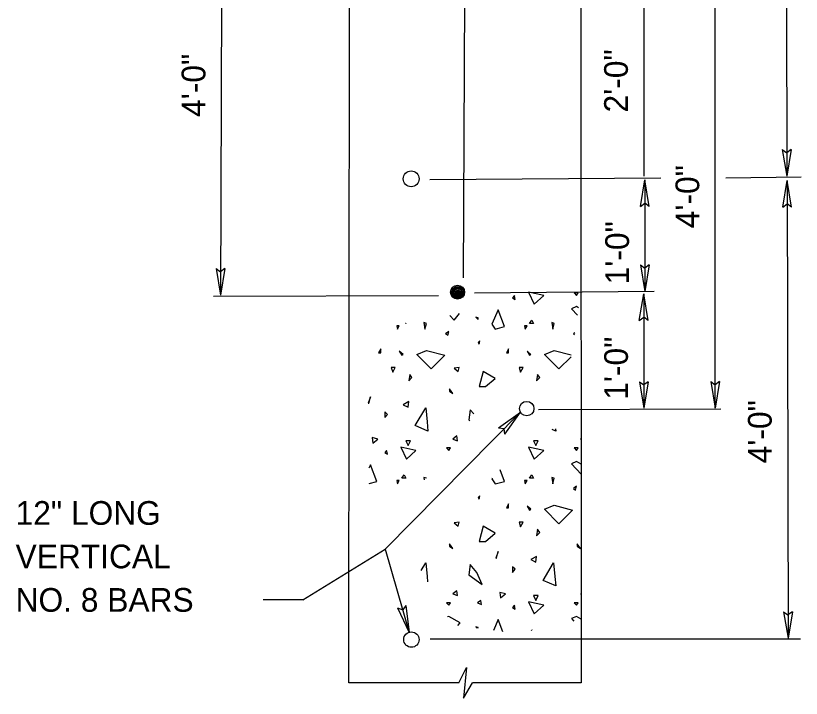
# Model space of a CAD drawing. Extents: x -0.8 to 6.5, y 10.6 to 20.8.
# Drawn here: x 4.207 to 6.193, y 12.966 to 14.693 of the extents above; entities that cross this region are included whole.
import ezdxf

# ---------------------------------------------------------------- set-up
doc = ezdxf.new("R2010")
doc.units = 0
for name, color, linetype in [('DETL-DIMS', 7, 'Continuous'), ('DETL-LINE', 7, 'Continuous'), ('DETL-NOTE', 7, 'Continuous'), ('DETL-PATT', 7, 'Continuous')]:
    doc.layers.add(name, color=color, linetype=linetype)

msp = doc.modelspace()

# ---------------------------------------------------------------- linework, layer by layer
at = {"layer": 'DETL-DIMS'}
for p, q in [((6.1547, 15.4506), (6.1565, 14.2871)), ((4.7284, 15.1604), (4.7241, 13.9861)), ((5.344, 15.1333), (5.338, 14.0301)), ((5.7946, 14.8825), (5.7949, 14.2867)), ((5.9756, 13.7003), (5.9749, 14.883)), ((6.1452, 14.3542), (6.1565, 14.2871)), ((6.1452, 14.3542), (6.1565, 14.3459)), ((6.1677, 14.3542), (6.1565, 14.2871)), ((6.1677, 14.3542), (6.1565, 14.3459)), ((6.002, 14.2831), (6.1932, 14.2851)), ((5.2538, 14.2789), (5.8384, 14.2824)), ((5.7866, 14.2104), (5.7977, 14.2776)), ((5.7977, 14.2776), (5.7972, 13.9956)), ((5.8089, 14.2103), (5.7977, 14.2776)), ((6.1462, 14.2086), (6.1572, 14.2759)), ((6.1572, 14.2759), (6.1597, 13.1183)), ((6.1685, 14.2088), (6.1572, 14.2759)), ((5.7866, 14.2104), (5.7977, 14.2187)), ((5.8089, 14.2103), (5.7977, 14.2187)), ((6.1462, 14.2086), (6.1574, 14.2171)), ((6.1685, 14.2088), (6.1574, 14.2171)), ((4.7131, 14.0534), (4.7241, 13.9861)), ((4.7131, 14.0534), (4.7243, 14.0449)), ((4.7356, 14.0533), (4.7241, 13.9861)), ((4.7356, 14.0533), (4.7243, 14.0449)), ((5.7863, 14.0629), (5.7972, 13.9956)), ((5.7863, 14.0629), (5.7974, 14.0544)), ((5.8086, 14.0628), (5.7972, 13.9956)), ((5.8086, 14.0628), (5.7974, 14.0544)), ((5.3667, 13.9921), (5.8214, 13.9961)), ((5.7836, 13.922), (5.7946, 13.9891)), ((5.7946, 13.9891), (5.7952, 13.7)), ((5.8059, 13.922), (5.7946, 13.9891)), ((4.7064, 13.9838), (5.2758, 13.9855)), ((5.7836, 13.922), (5.7946, 13.9305)), ((5.8059, 13.922), (5.7946, 13.9305)), ((5.7838, 13.7672), (5.7952, 13.7)), ((5.7838, 13.7672), (5.7951, 13.7588)), ((5.8062, 13.7672), (5.7951, 13.7588)), ((5.8062, 13.7672), (5.7952, 13.7)), ((5.9642, 13.7675), (5.9756, 13.7003)), ((5.9642, 13.7675), (5.9756, 13.7592)), ((5.9867, 13.7675), (5.9756, 13.7003)), ((5.9867, 13.7675), (5.9756, 13.7592)), ((5.1409, 13.3439), (5.483, 13.6903)), ((5.4276, 13.6503), (5.483, 13.6903)), ((5.4436, 13.6345), (5.483, 13.6903)), ((5.529, 13.6967), (5.9894, 13.6988)), ((5.4276, 13.6503), (5.4416, 13.6485)), ((5.4436, 13.6345), (5.4416, 13.6485)), ((4.9326, 13.2152), (5.1409, 13.3439)), ((5.1409, 13.3439), (5.2013, 13.1331)), ((4.9326, 13.2152), (4.8326, 13.2152)), ((5.172, 13.1947), (5.2013, 13.1331)), ((5.172, 13.1947), (5.1852, 13.1897)), ((5.1935, 13.2007), (5.1852, 13.1897)), ((5.1935, 13.2007), (5.2013, 13.1331)), ((6.1482, 13.1854), (6.1597, 13.1183)), ((6.1482, 13.1854), (6.1595, 13.1771)), ((6.1707, 13.1854), (6.1595, 13.1771)), ((6.1707, 13.1854), (6.1597, 13.1183)), ((5.2548, 13.1171), (6.1915, 13.1168))]:
    msp.add_line(p, q, dxfattribs=at)
at = {"layer": 'DETL-LINE'}
for p, q in [((5.0487, 13.0051), (5.052, 15.599)), ((5.6349, 15.5982), (5.6368, 13.0051)), ((5.327, 13.0051), (5.3462, 13.0438)), ((5.3462, 13.0438), (5.3392, 12.9663)), ((5.327, 13.0051), (5.0487, 13.0051)), ((5.3392, 12.9663), (5.3615, 13.0051)), ((5.6368, 13.0051), (5.3615, 13.0051))]:
    msp.add_line(p, q, dxfattribs=at)
for centre, radius in [((5.2066, 14.2802), 0.02), ((5.3239, 13.9935), 0.0177), ((5.3244, 13.9925), 0.0155), ((5.3244, 13.9925), 0.0134), ((5.3242, 13.9925), 0.0115), ((5.3248, 13.992), 0.0101), ((5.3253, 13.9908), 0.00797), ((5.3253, 13.9906), 0.0059), ((5.3251, 13.9906), 0.00398), ((5.3255, 13.9906), 0.00188), ((5.4988, 13.6991), 0.0182), ((5.2071, 13.1147), 0.0194)]:
    msp.add_circle(centre, radius, dxfattribs=at)
at = {"layer": 'DETL-PATT'}
for points in [[(5.5035, 13.9935), (5.5178, 13.9631), (5.5418, 13.9853)], [(5.6186, 13.9915), (5.6249, 13.9853), (5.6288, 13.9915)], [(5.4631, 13.979), (5.4693, 13.9751), (5.4675, 13.9853)], [(5.419, 13.9003), (5.443, 13.9065), (5.4266, 13.9488), (5.4108, 13.9128)], [(5.3761, 13.9286), (5.3705, 13.9306), (5.3761, 13.9248)], [(5.1703, 13.9085), (5.1722, 13.9003), (5.1765, 13.9085)], [(5.239, 13.9166), (5.2413, 13.9003), (5.2452, 13.9146)], [(5.4933, 13.9085), (5.4953, 13.9003), (5.4996, 13.9085)], [(5.5116, 13.9228), (5.516, 13.9146), (5.5058, 13.9146)], [(5.562, 13.9166), (5.5645, 13.9003), (5.5683, 13.9146)], [(5.2937, 13.8883), (5.2995, 13.8845), (5.3018, 13.8945)], [(5.3805, 13.8701), (5.3761, 13.8663), (5.3786, 13.862)], [(5.13, 13.85), (5.1242, 13.8398), (5.13, 13.8398)], [(5.453, 13.85), (5.4473, 13.8398), (5.453, 13.8398)], [(5.1828, 13.8341), (5.1867, 13.836), (5.1765, 13.8441)], [(5.2452, 13.8461), (5.2917, 13.8341), (5.2572, 13.7995), (5.2207, 13.836)], [(5.5058, 13.8341), (5.5096, 13.836), (5.4996, 13.8441)], [(5.1564, 13.8033), (5.1602, 13.7913), (5.1665, 13.8033)], [(5.3157, 13.8015), (5.3258, 13.7933), (5.3278, 13.8033)], [(5.3945, 13.7548), (5.419, 13.7755), (5.3886, 13.7933), (5.3786, 13.7548)], [(5.4795, 13.8033), (5.4833, 13.7913), (5.4895, 13.8033)], [(5.203, 13.7857), (5.2005, 13.7693), (5.2087, 13.7775)], [(5.526, 13.7857), (5.5236, 13.7693), (5.5318, 13.7775)], [(5.3037, 13.7492), (5.3037, 13.7428), (5.3118, 13.7372)], [(5.0979, 13.7127), (5.0997, 13.7127), (5.1035, 13.729)], [(5.1867, 13.7088), (5.1987, 13.7025), (5.2005, 13.717)], [(5.14, 13.6905), (5.14, 13.6762), (5.1464, 13.6843)], [(5.2472, 13.666), (5.249, 13.642), (5.2168, 13.656), (5.2433, 13.7007)], [(5.322, 13.63), (5.3118, 13.6218), (5.3238, 13.6175)], [(5.1079, 13.6257), (5.1099, 13.6118), (5.1219, 13.6218)], [(5.1928, 13.6175), (5.1987, 13.6055), (5.2048, 13.6175)], [(5.516, 13.6175), (5.5216, 13.6055), (5.528, 13.6175)], [(5.14, 13.5873), (5.1464, 13.5835), (5.1444, 13.5935)], [(5.1803, 13.6017), (5.1948, 13.5715), (5.2188, 13.5935)], [(5.2957, 13.5998), (5.3018, 13.5935), (5.3057, 13.5998)], [(5.5035, 13.6017), (5.5178, 13.5715), (5.5418, 13.5935)], [(5.6186, 13.5998), (5.6249, 13.5935), (5.6288, 13.5998)], [(5.1885, 13.5312), (5.1928, 13.523), (5.1828, 13.523)], [(5.5116, 13.5312), (5.516, 13.523), (5.5058, 13.523)], [(5.1703, 13.5169), (5.1722, 13.5087), (5.1765, 13.5169)], [(5.4933, 13.5169), (5.4953, 13.5087), (5.4996, 13.5169)], [(5.562, 13.525), (5.5645, 13.5087), (5.5683, 13.523)], [(5.6168, 13.4967), (5.6224, 13.4929), (5.6249, 13.5029)], [(5.3805, 13.4784), (5.3761, 13.4745), (5.3786, 13.4702)], [(5.453, 13.4582), (5.4473, 13.4482), (5.453, 13.4482)], [(5.5058, 13.4424), (5.5096, 13.4444), (5.4996, 13.4525)], [(5.5683, 13.4544), (5.6148, 13.4424), (5.5803, 13.4079), (5.5438, 13.4444)], [(5.3157, 13.4097), (5.3258, 13.4015), (5.3278, 13.4117)], [(5.4795, 13.4117), (5.4833, 13.3997), (5.4895, 13.4117)], [(5.3945, 13.3632), (5.419, 13.3839), (5.3886, 13.4015), (5.3786, 13.3632)], [(5.526, 13.3939), (5.5236, 13.3775), (5.5318, 13.3857)], [(5.3037, 13.3574), (5.3037, 13.3512), (5.3118, 13.3454)], [(5.6268, 13.3574), (5.6268, 13.3512), (5.6349, 13.3454)], [(5.4208, 13.3209), (5.4228, 13.3209), (5.4266, 13.3372)], [(5.5096, 13.3171), (5.5216, 13.3109), (5.5236, 13.3252)], [(5.356, 13.3046), (5.3522, 13.2787), (5.3863, 13.2542), (5.3723, 13.2844)], [(5.4631, 13.2989), (5.4631, 13.2844), (5.4693, 13.2926)], [(5.5701, 13.2744), (5.5721, 13.2504), (5.54, 13.2642), (5.5663, 13.3089)], [(5.322, 13.2384), (5.3118, 13.2302), (5.3238, 13.2259)], [(5.431, 13.2341), (5.4328, 13.2201), (5.4448, 13.2302)], [(5.3743, 13.2081), (5.3843, 13.2037), (5.3825, 13.2139)], [(5.516, 13.2259), (5.5216, 13.2139), (5.528, 13.2259)], [(5.2957, 13.2081), (5.3018, 13.2019), (5.3057, 13.2081)], [(5.4631, 13.1957), (5.4693, 13.1917), (5.4675, 13.2019)], [(5.5035, 13.2101), (5.5178, 13.1797), (5.5418, 13.2019)], [(5.6186, 13.2081), (5.6249, 13.2019), (5.6288, 13.2081)]]:
    msp.add_lwpolyline(points, close=True, dxfattribs=at)
for points in [[(5.6298, 13.9541), (5.6249, 13.957), (5.6124, 13.9511), (5.6269, 13.9356)], [(5.3045, 13.935), (5.3157, 13.9228), (5.3292, 13.9395)], [(5.1928, 13.9148), (5.1928, 13.9146), (5.192, 13.9146)], [(5.6201, 13.891), (5.6168, 13.8883), (5.6194, 13.8865)], [(5.6109, 13.8303), (5.5803, 13.7995), (5.5438, 13.836), (5.5683, 13.8461), (5.6116, 13.8348)], [(5.3648, 13.6855), (5.356, 13.6963), (5.3522, 13.6703), (5.3547, 13.6687)], [(5.5715, 13.6483), (5.5721, 13.642), (5.563, 13.646)], [(5.6368, 13.6235), (5.6349, 13.6218), (5.6368, 13.6213)], [(5.1, 13.5097), (5.1199, 13.5149), (5.1035, 13.5572), (5.0995, 13.548)], [(5.6368, 13.5584), (5.6249, 13.5652), (5.6124, 13.5595), (5.6368, 13.5334)], [(5.4116, 13.5232), (5.4108, 13.521), (5.419, 13.5087), (5.443, 13.5149), (5.4316, 13.544)], [(5.2452, 13.5229), (5.2452, 13.523), (5.239, 13.525), (5.2398, 13.5189)], [(5.2318, 13.2896), (5.2433, 13.3089), (5.2472, 13.2744), (5.2482, 13.2609)], [(5.6368, 13.2317), (5.6349, 13.2302), (5.6368, 13.2296)], [(5.3248, 13.1508), (5.3302, 13.1573), (5.3018, 13.1736), (5.2987, 13.1721)], [(5.6368, 13.1667), (5.6249, 13.1736), (5.6124, 13.1677), (5.6183, 13.1614)], [(5.4385, 13.1348), (5.4266, 13.1654), (5.4145, 13.1381)], [(5.3761, 13.1436), (5.3761, 13.1453), (5.3705, 13.1473), (5.3738, 13.1438)], [(5.5105, 13.1379), (5.5116, 13.1396), (5.5123, 13.1383)]]:
    msp.add_lwpolyline(points, dxfattribs=at)

# ---------------------------------------------------------------- texts
at = {"layer": 'DETL-NOTE'}
for s, p in [('2\'-0"', (5.7546, 14.4482)), ('4\'-0"', (4.6862, 14.4369)), ('4\'-0"', (5.9351, 14.1553)), ('1\'-0"', (5.7575, 14.0134)), ('1\'-0"', (5.7548, 13.7214)), ('4\'-0"', (6.1183, 13.5607))]:
    msp.add_text(s, height=0.06, rotation=90, dxfattribs=at).set_placement(p)
for s, p in [('12" LONG', (4.2062, 13.4051)), ('VERTICAL', (4.2062, 13.2951)), ('NO. 8 BARS', (4.2062, 13.1852))]:
    msp.add_text(s, height=0.06, dxfattribs=at).set_placement(p)

doc.saveas('drawing.dxf')
